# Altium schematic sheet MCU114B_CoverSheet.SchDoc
size 431 x 279 mm; Date: Not shown in title block; ApprovedBy: Not shown in title block; CheckedBy: Not shown in title block; Author: Not shown in title block; CompanyName: Not shown in title block; Engineer: Not shown in title block; Organization: Not shown in title block; Address1: Not shown in title block; Address2: Not shown in title block; Address3: Not shown in title block; Address4: Not shown in title block; DocumentNumber: 1; Revision: Use project parameter SCH_Rev; SheetNumber: 1; SheetTotal: 11; PageSetup: Record=PageOptions¦CenterHorizontal=True¦CenterVertical=True¦PrintScale=1.00¦XCorrection=1.00¦YCorrection=1.00¦PrintKind=0¦BorderSize=5000000¦LeftOffset=0¦BottomOffset=0¦Orientation=2¦PaperLength=1000¦PaperWidth=1000¦Scale=100¦PaperSource=15¦PrintQuality=600¦MediaType=1¦DitherType=10¦PaperKind=Letter¦PrintScaleMode=1
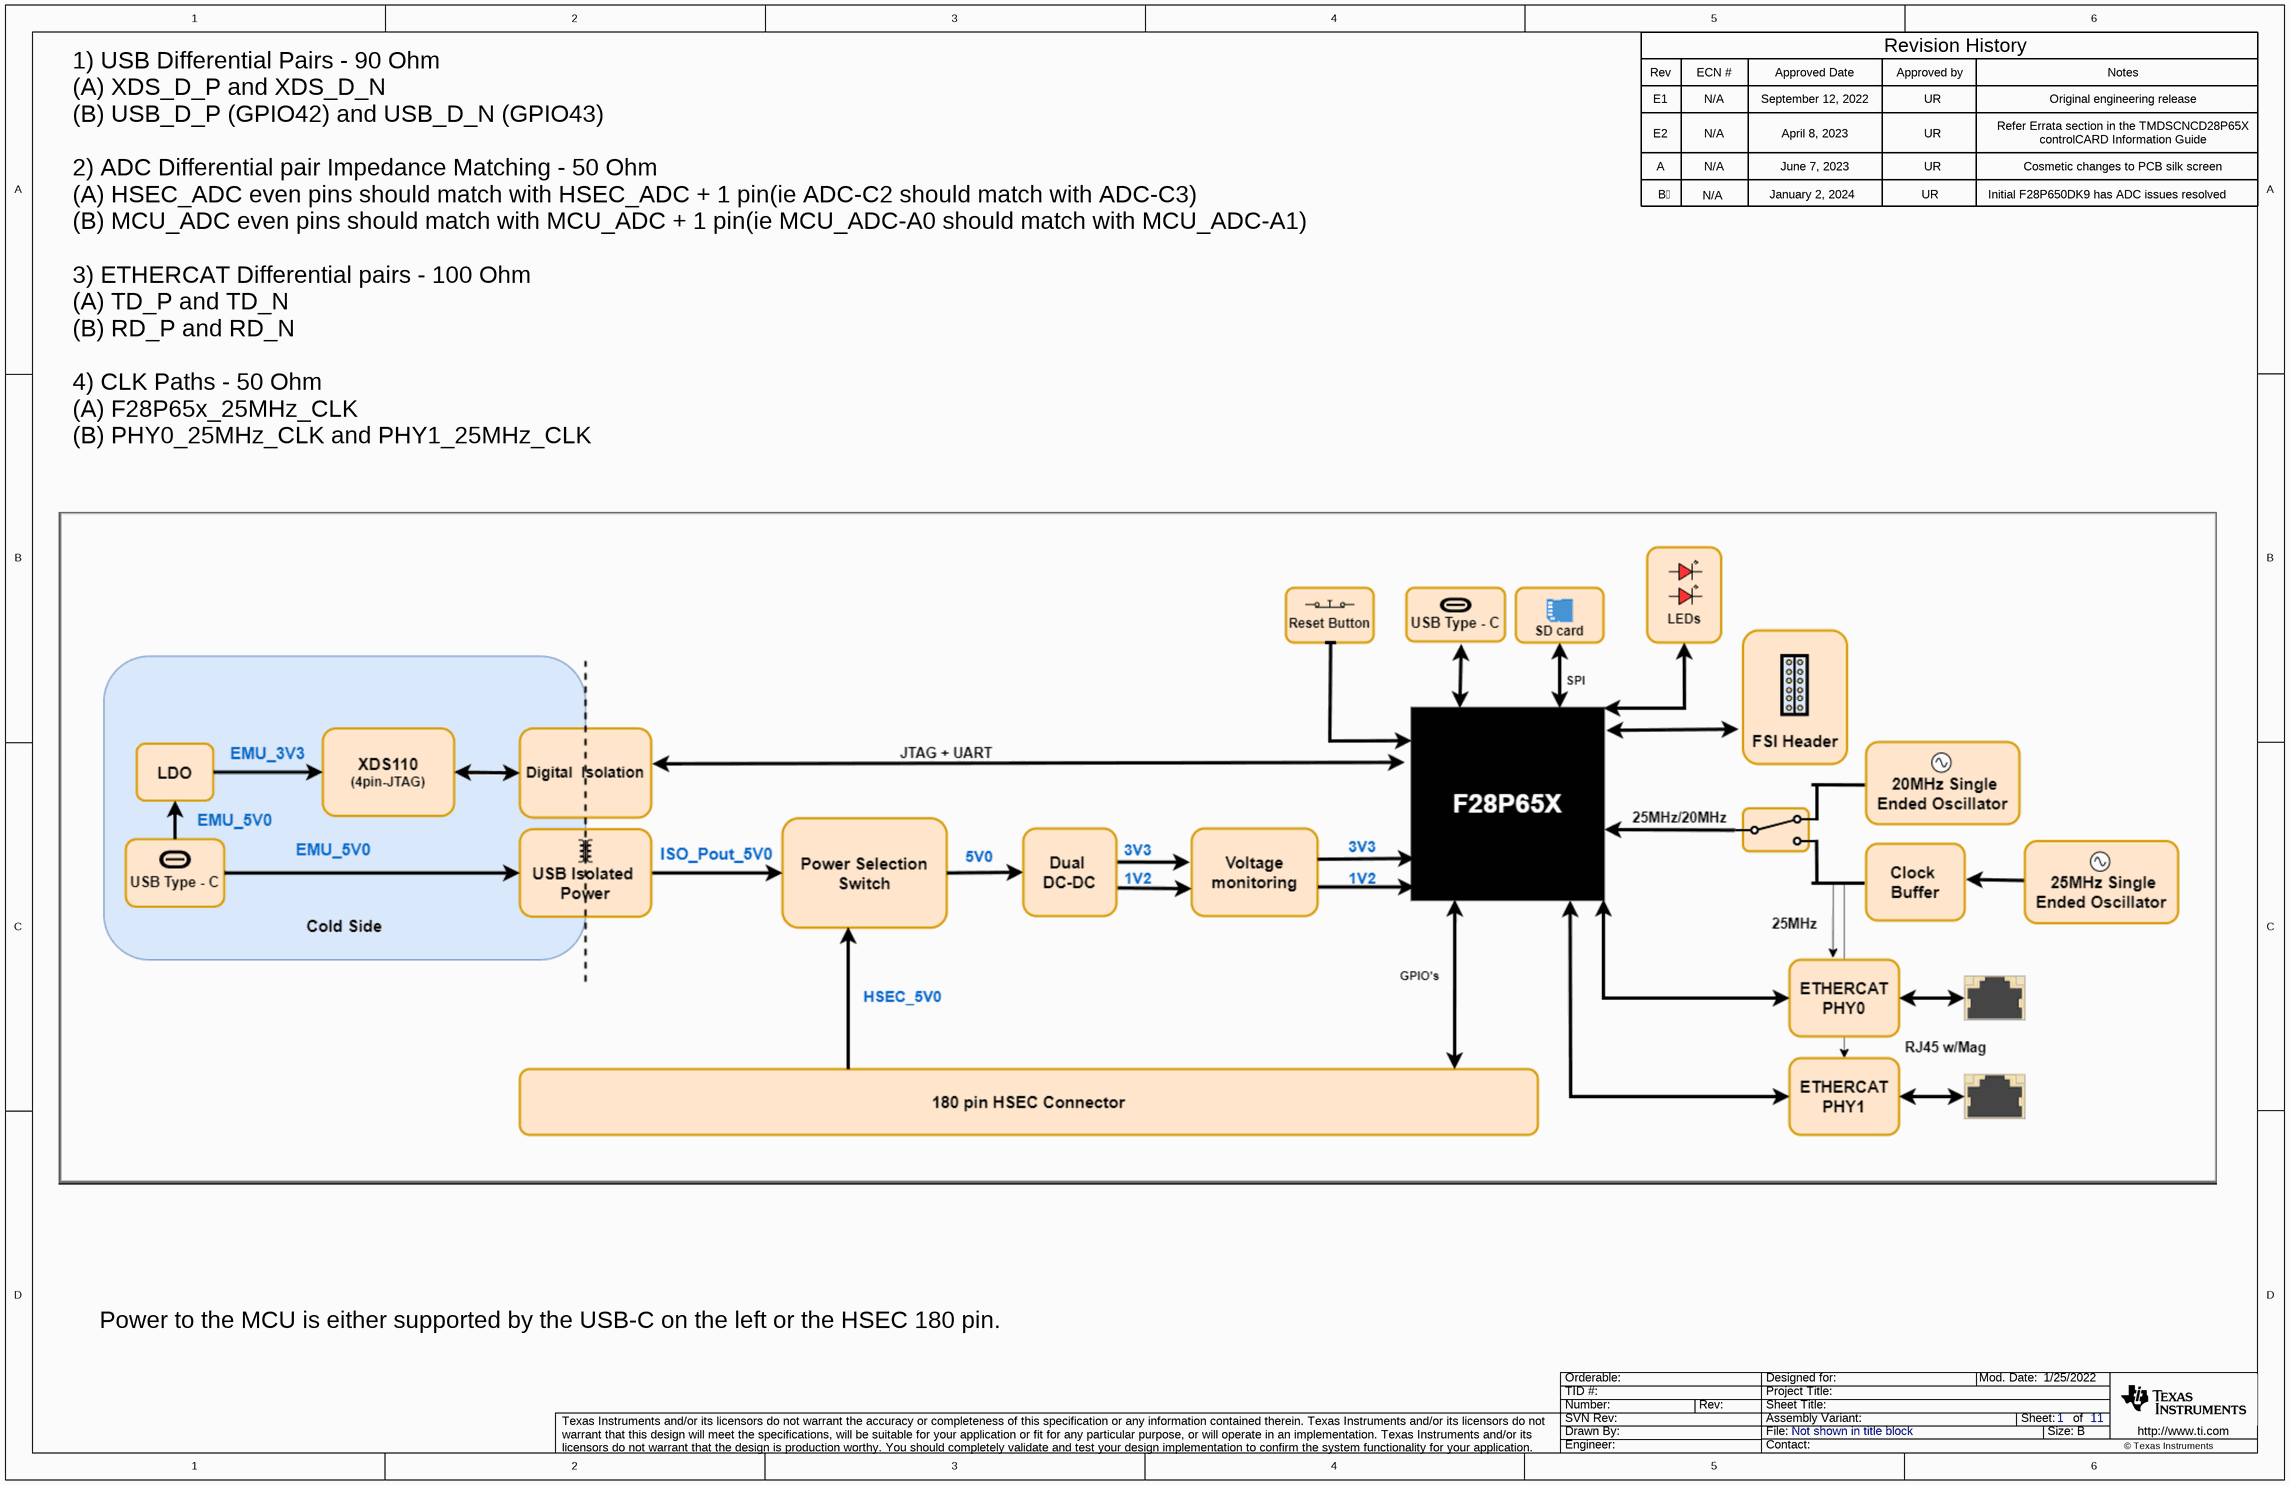
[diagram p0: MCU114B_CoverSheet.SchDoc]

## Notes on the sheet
- Rev
- E1
- ECN #
- N/A
- Approved Date
- September 12, 2022
- Approved by
- UR
- Revision History
- Notes
- Original engineering release
- E2
- A
- April 8, 2023
- June 7, 2023
- Refer Errata section in the TMDSCNCD28P65X
- controlCARD Information Guide
- Cosmetic changes to PCB silk screen
- B
- January 2, 2024
- Initial F28P650DK9 has ADC issues resolved
- 1) USB Differential Pairs - 90 Ohm
  (A) XDS_D_P and XDS_D_N
  (B) USB_D_P (GPIO42) and USB_D_N (GPIO43)
  2) ADC Differential pair Impedance Matching - 50 Ohm
  (A) HSEC_ADC even pins should match with HSEC_ADC + 1 pin(ie ADC-C2 should match with ADC-C3)
  (B) MCU_ADC even pins should match with MCU_ADC + 1 pin(ie MCU_ADC-A0 should match with MCU_ADC-A1)
  3) ETHERCAT Differential pairs - 100 Ohm
  (A) TD_P and TD_N
  (B) RD_P and RD_N
  4) CLK Paths - 50 Ohm
  (A) F28P65x_25MHz_CLK
  (B) PHY0_25MHz_CLK and PHY1_25MHz_CLK
- Power to the MCU is either supported by the USB-C on the left or the HSEC 180 pin.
